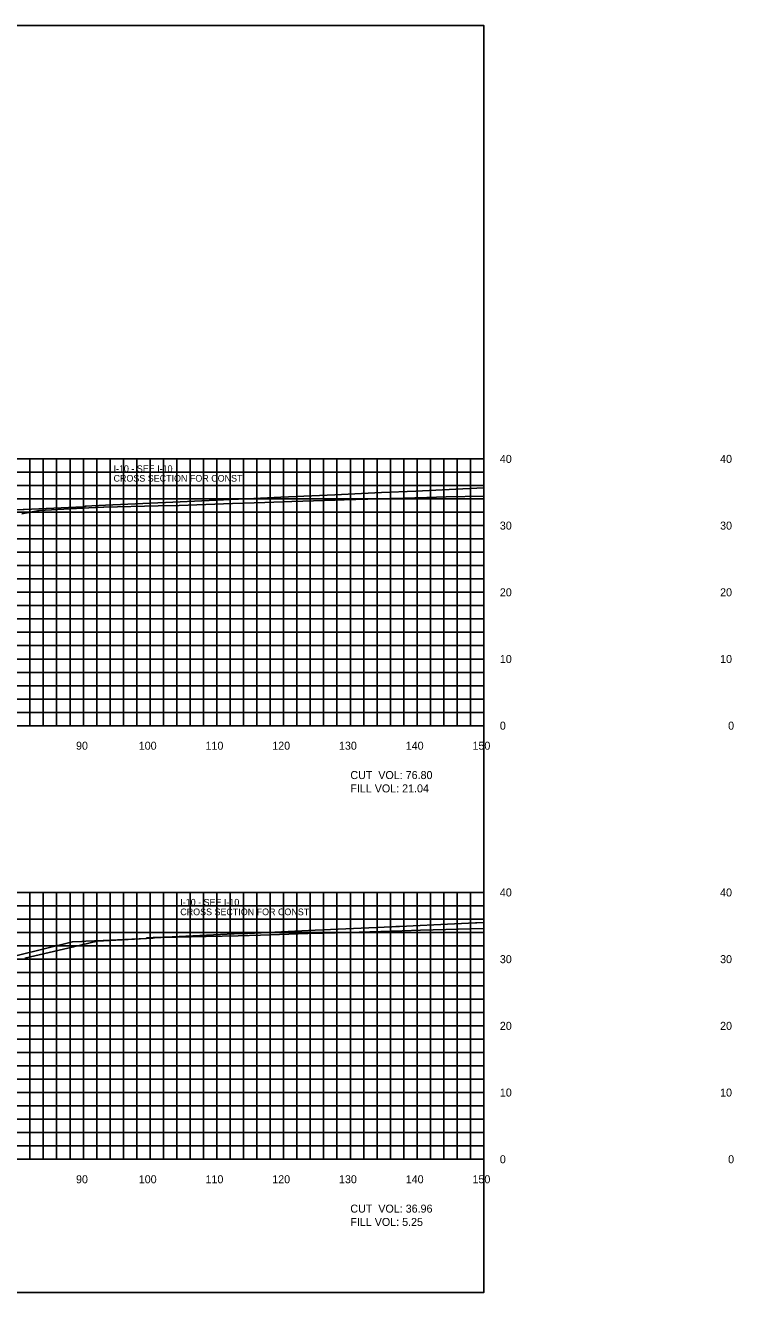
# Model space of a CAD drawing. Extents: x 1797652 to 1804159, y 242516 to 246906.
# Drawn here: x 1802725.8 to 1802831.9, y 242516 to 242706 of the extents above; entities that cross this region are included whole.
import ezdxf

# ---------------------------------------------------------------- set-up
doc = ezdxf.new("R2010")
doc.units = 0
for name, color, linetype in [('10', 7, 'Continuous'), ('3', 7, 'Continuous'), ('31', 7, 'Continuous'), ('60', 7, 'Continuous'), ('CL-CNST', 7, 'Continuous'), ('Level 62', 7, 'Continuous'), ('M-ROADS', 7, 'Continuous')]:
    doc.layers.add(name, color=color, linetype=linetype)

msp = doc.modelspace()

# ---------------------------------------------------------------- linework, layer by layer
msp.add_lwpolyline([(1802494.49, 242516), (1802794.49, 242516), (1802794.49, 242706), (1802494.49, 242706)], close=True)
at = {"layer": '60'}
for p, q in [((1802794.49, 242601), (1802794.49, 242641)), ((1802794.55, 242641), (1802794.49, 242641)), ((1802794.55, 242631), (1802794.49, 242631)), ((1802794.55, 242621), (1802794.49, 242621)), ((1802794.55, 242611), (1802794.49, 242611)), ((1802494.49, 242601), (1802794.49, 242601)), ((1802734.49, 242600.94), (1802734.49, 242601)), ((1802744.49, 242600.94), (1802744.49, 242601)), ((1802754.49, 242600.94), (1802754.49, 242601)), ((1802764.49, 242600.94), (1802764.49, 242601)), ((1802774.49, 242600.94), (1802774.49, 242601)), ((1802784.49, 242600.94), (1802784.49, 242601)), ((1802794.49, 242600.94), (1802794.49, 242601)), ((1802794.55, 242601), (1802794.49, 242601)), ((1802794.49, 242536), (1802794.49, 242576)), ((1802794.55, 242576), (1802794.49, 242576)), ((1802794.55, 242566), (1802794.49, 242566)), ((1802794.55, 242556), (1802794.49, 242556)), ((1802794.55, 242546), (1802794.49, 242546)), ((1802494.49, 242536), (1802794.49, 242536)), ((1802734.49, 242535.94), (1802734.49, 242536)), ((1802744.49, 242535.94), (1802744.49, 242536)), ((1802754.49, 242535.94), (1802754.49, 242536)), ((1802764.49, 242535.94), (1802764.49, 242536)), ((1802774.49, 242535.94), (1802774.49, 242536)), ((1802784.49, 242535.94), (1802784.49, 242536)), ((1802794.49, 242535.94), (1802794.49, 242536)), ((1802794.55, 242536), (1802794.49, 242536))]:
    msp.add_line(p, q, dxfattribs=at)
at = {"layer": 'CL-CNST'}
for points in [[(1802674.99, 242621.26), (1802710.86, 242630.15), (1802723.62, 242633.31), (1802725.45, 242633.4), (1802725.64, 242633.41), (1802733.38, 242633.76), (1802734.66, 242633.82), (1802734.73, 242633.89), (1802734.74, 242633.9), (1802734.9, 242633.91), (1802735.76, 242633.94), (1802737.81, 242634.04), (1802747.89, 242634.5), (1802756.56, 242634.9), (1802760.03, 242635.06), (1802764.06, 242635.25), (1802772.17, 242635.62), (1802779.15, 242635.94), (1802784.31, 242636.18), (1802790.28, 242636.45), (1802794.49, 242636.65)], [(1802673.48, 242553.88), (1802703.92, 242561.43), (1802732.86, 242568.6), (1802734.25, 242568.67), (1802734.88, 242568.7), (1802737.48, 242568.81), (1802743.88, 242569.11), (1802743.94, 242569.17), (1802743.96, 242569.19), (1802744.22, 242569.2), (1802744.97, 242569.23), (1802747.78, 242569.36), (1802757.09, 242569.78), (1802759.14, 242569.87), (1802769.2, 242570.33), (1802780.7, 242570.86), (1802781.32, 242570.89), (1802781.86, 242570.91), (1802790.1, 242571.29), (1802793.23, 242571.43), (1802793.43, 242571.44), (1802794.49, 242571.49)]]:
    msp.add_lwpolyline(points, dxfattribs=at)
at = {"layer": 'Level 62'}
for p, q in [((1802494.49, 242641), (1802794.49, 242641)), ((1802726.49, 242601), (1802726.49, 242641)), ((1802728.49, 242601), (1802728.49, 242641)), ((1802730.49, 242601), (1802730.49, 242641)), ((1802732.49, 242601), (1802732.49, 242641)), ((1802734.49, 242601), (1802734.49, 242641)), ((1802736.49, 242601), (1802736.49, 242641)), ((1802738.49, 242601), (1802738.49, 242641)), ((1802740.49, 242601), (1802740.49, 242641)), ((1802742.49, 242601), (1802742.49, 242641)), ((1802744.49, 242601), (1802744.49, 242641)), ((1802746.49, 242601), (1802746.49, 242641)), ((1802748.49, 242601), (1802748.49, 242641)), ((1802750.49, 242601), (1802750.49, 242641)), ((1802752.49, 242601), (1802752.49, 242641)), ((1802754.49, 242601), (1802754.49, 242641)), ((1802756.49, 242601), (1802756.49, 242641)), ((1802758.49, 242601), (1802758.49, 242641)), ((1802760.49, 242601), (1802760.49, 242641)), ((1802762.49, 242601), (1802762.49, 242641)), ((1802764.49, 242601), (1802764.49, 242641)), ((1802766.49, 242601), (1802766.49, 242641)), ((1802768.49, 242601), (1802768.49, 242641)), ((1802770.49, 242601), (1802770.49, 242641)), ((1802772.49, 242601), (1802772.49, 242641)), ((1802774.49, 242601), (1802774.49, 242641)), ((1802776.49, 242601), (1802776.49, 242641)), ((1802778.49, 242601), (1802778.49, 242641)), ((1802780.49, 242601), (1802780.49, 242641)), ((1802782.49, 242601), (1802782.49, 242641)), ((1802784.49, 242601), (1802784.49, 242641)), ((1802786.49, 242601), (1802786.49, 242641)), ((1802788.49, 242601), (1802788.49, 242641)), ((1802790.49, 242601), (1802790.49, 242641)), ((1802792.49, 242601), (1802792.49, 242641)), ((1802794.49, 242601), (1802794.49, 242641)), ((1802494.49, 242639), (1802794.49, 242639)), ((1802494.49, 242637), (1802794.49, 242637)), ((1802494.49, 242635), (1802794.49, 242635)), ((1802494.49, 242633), (1802794.49, 242633)), ((1802494.49, 242631), (1802794.49, 242631)), ((1802494.49, 242629), (1802794.49, 242629)), ((1802494.49, 242627), (1802794.49, 242627)), ((1802494.49, 242625), (1802794.49, 242625)), ((1802494.49, 242623), (1802794.49, 242623)), ((1802494.49, 242621), (1802794.49, 242621)), ((1802494.49, 242619), (1802794.49, 242619)), ((1802494.49, 242617), (1802794.49, 242617)), ((1802494.49, 242615), (1802794.49, 242615)), ((1802494.49, 242613), (1802794.49, 242613)), ((1802494.49, 242611), (1802794.49, 242611)), ((1802494.49, 242609), (1802794.49, 242609)), ((1802494.49, 242607), (1802794.49, 242607)), ((1802494.49, 242605), (1802794.49, 242605)), ((1802494.49, 242603), (1802794.49, 242603)), ((1802494.49, 242601), (1802794.49, 242601)), ((1802494.49, 242576), (1802794.49, 242576)), ((1802726.49, 242536), (1802726.49, 242576)), ((1802728.49, 242536), (1802728.49, 242576)), ((1802730.49, 242536), (1802730.49, 242576)), ((1802732.49, 242536), (1802732.49, 242576)), ((1802734.49, 242536), (1802734.49, 242576)), ((1802736.49, 242536), (1802736.49, 242576)), ((1802738.49, 242536), (1802738.49, 242576)), ((1802740.49, 242536), (1802740.49, 242576)), ((1802742.49, 242536), (1802742.49, 242576)), ((1802744.49, 242536), (1802744.49, 242576)), ((1802746.49, 242536), (1802746.49, 242576)), ((1802748.49, 242536), (1802748.49, 242576)), ((1802750.49, 242536), (1802750.49, 242576)), ((1802752.49, 242536), (1802752.49, 242576)), ((1802754.49, 242536), (1802754.49, 242576)), ((1802756.49, 242536), (1802756.49, 242576)), ((1802758.49, 242536), (1802758.49, 242576)), ((1802760.49, 242536), (1802760.49, 242576)), ((1802762.49, 242536), (1802762.49, 242576)), ((1802764.49, 242536), (1802764.49, 242576)), ((1802766.49, 242536), (1802766.49, 242576)), ((1802768.49, 242536), (1802768.49, 242576)), ((1802770.49, 242536), (1802770.49, 242576)), ((1802772.49, 242536), (1802772.49, 242576)), ((1802774.49, 242536), (1802774.49, 242576)), ((1802776.49, 242536), (1802776.49, 242576)), ((1802778.49, 242536), (1802778.49, 242576)), ((1802780.49, 242536), (1802780.49, 242576)), ((1802782.49, 242536), (1802782.49, 242576)), ((1802784.49, 242536), (1802784.49, 242576)), ((1802786.49, 242536), (1802786.49, 242576)), ((1802788.49, 242536), (1802788.49, 242576)), ((1802790.49, 242536), (1802790.49, 242576)), ((1802792.49, 242536), (1802792.49, 242576)), ((1802794.49, 242536), (1802794.49, 242576)), ((1802494.49, 242574), (1802794.49, 242574)), ((1802494.49, 242572), (1802794.49, 242572)), ((1802494.49, 242570), (1802794.49, 242570)), ((1802494.49, 242568), (1802794.49, 242568)), ((1802494.49, 242566), (1802794.49, 242566)), ((1802494.49, 242564), (1802794.49, 242564)), ((1802494.49, 242562), (1802794.49, 242562)), ((1802494.49, 242560), (1802794.49, 242560)), ((1802494.49, 242558), (1802794.49, 242558)), ((1802494.49, 242556), (1802794.49, 242556)), ((1802494.49, 242554), (1802794.49, 242554)), ((1802494.49, 242552), (1802794.49, 242552)), ((1802494.49, 242550), (1802794.49, 242550)), ((1802494.49, 242548), (1802794.49, 242548)), ((1802494.49, 242546), (1802794.49, 242546)), ((1802494.49, 242544), (1802794.49, 242544)), ((1802494.49, 242542), (1802794.49, 242542)), ((1802494.49, 242540), (1802794.49, 242540)), ((1802494.49, 242538), (1802794.49, 242538)), ((1802494.49, 242536), (1802794.49, 242536))]:
    msp.add_line(p, q, dxfattribs=at)
at = {"layer": 'M-ROADS'}
for points in [[(1802725.27, 242632.77), (1802727.88, 242633.26), (1802731.55, 242633.46), (1802736.26, 242633.69), (1802736.37, 242633.7), (1802737.52, 242633.77), (1802737.53, 242633.77), (1802737.57, 242633.77), (1802745.69, 242633.96), (1802748.83, 242634.03), (1802756.81, 242634.31), (1802761.68, 242634.48), (1802765.73, 242634.61), (1802770.64, 242634.76), (1802772.24, 242634.81), (1802773.58, 242634.85), (1802784.14, 242635.17), (1802785.93, 242635.22), (1802788.85, 242635.29), (1802794.49, 242635.41)], [(1802725.72, 242566.13), (1802733.03, 242567.84), (1802736.56, 242568.7), (1802742.17, 242569.01), (1802743.96, 242569.11), (1802744.91, 242569.16), (1802745.15, 242569.18), (1802746.16, 242569.24), (1802752.91, 242569.39), (1802757.66, 242569.48), (1802761.03, 242569.58), (1802765.26, 242569.74), (1802768.14, 242569.83), (1802770.45, 242569.91), (1802775.82, 242570.07), (1802782.27, 242570.27), (1802785, 242570.34), (1802794.45, 242570.62), (1802794.49, 242570.62)]]:
    msp.add_lwpolyline(points, dxfattribs=at)

# ---------------------------------------------------------------- texts
at = {"layer": '10'}
for s, p in [('90', (1802733.39, 242597.4)), ('100', (1802742.79, 242597.4)), ('110', (1802752.79, 242597.4)), ('120', (1802762.79, 242597.4)), ('130', (1802772.79, 242597.4)), ('140', (1802782.79, 242597.4)), ('150', (1802792.79, 242597.4)), ('CUT  VOL: 76.80', (1802774.49, 242593)), ('FILL VOL: 21.04', (1802774.49, 242591)), ('90', (1802733.39, 242532.4)), ('100', (1802742.79, 242532.4)), ('110', (1802752.79, 242532.4)), ('120', (1802762.79, 242532.4)), ('130', (1802772.79, 242532.4)), ('140', (1802782.79, 242532.4)), ('150', (1802792.79, 242532.4)), ('CUT  VOL: 36.96', (1802774.49, 242528)), ('FILL VOL: 5.25', (1802774.49, 242526))]:
    msp.add_text(s, height=1.2, dxfattribs=at).set_placement(p)
at = {"layer": '3'}
for s, p in [('I-10 - SEE I-10', (1802739.01, 242639.03)), ('CROSS SECTION FOR CONST ', (1802739.01, 242637.59)), ('I-10 - SEE I-10', (1802749.01, 242574.03)), ('CROSS SECTION FOR CONST ', (1802749.01, 242572.59))]:
    msp.add_text(s, height=1, dxfattribs=at).set_placement(p)
at = {"layer": '31'}
for s, p in [('40', (1802796.89, 242640.4)), ('40', (1802829.89, 242640.4)), ('30', (1802796.89, 242630.4)), ('30', (1802829.89, 242630.4)), ('20', (1802796.89, 242620.4)), ('20', (1802829.89, 242620.4)), ('10', (1802796.89, 242610.4)), ('10', (1802829.89, 242610.4)), ('0', (1802796.89, 242600.4)), ('0', (1802831.09, 242600.4)), ('40', (1802796.89, 242575.4)), ('40', (1802829.89, 242575.4)), ('30', (1802796.89, 242565.4)), ('30', (1802829.89, 242565.4)), ('20', (1802796.89, 242555.4)), ('20', (1802829.89, 242555.4)), ('10', (1802796.89, 242545.4)), ('10', (1802829.89, 242545.4)), ('0', (1802796.89, 242535.4)), ('0', (1802831.09, 242535.4))]:
    msp.add_text(s, height=1.2, dxfattribs=at).set_placement(p)

doc.saveas('drawing.dxf')
